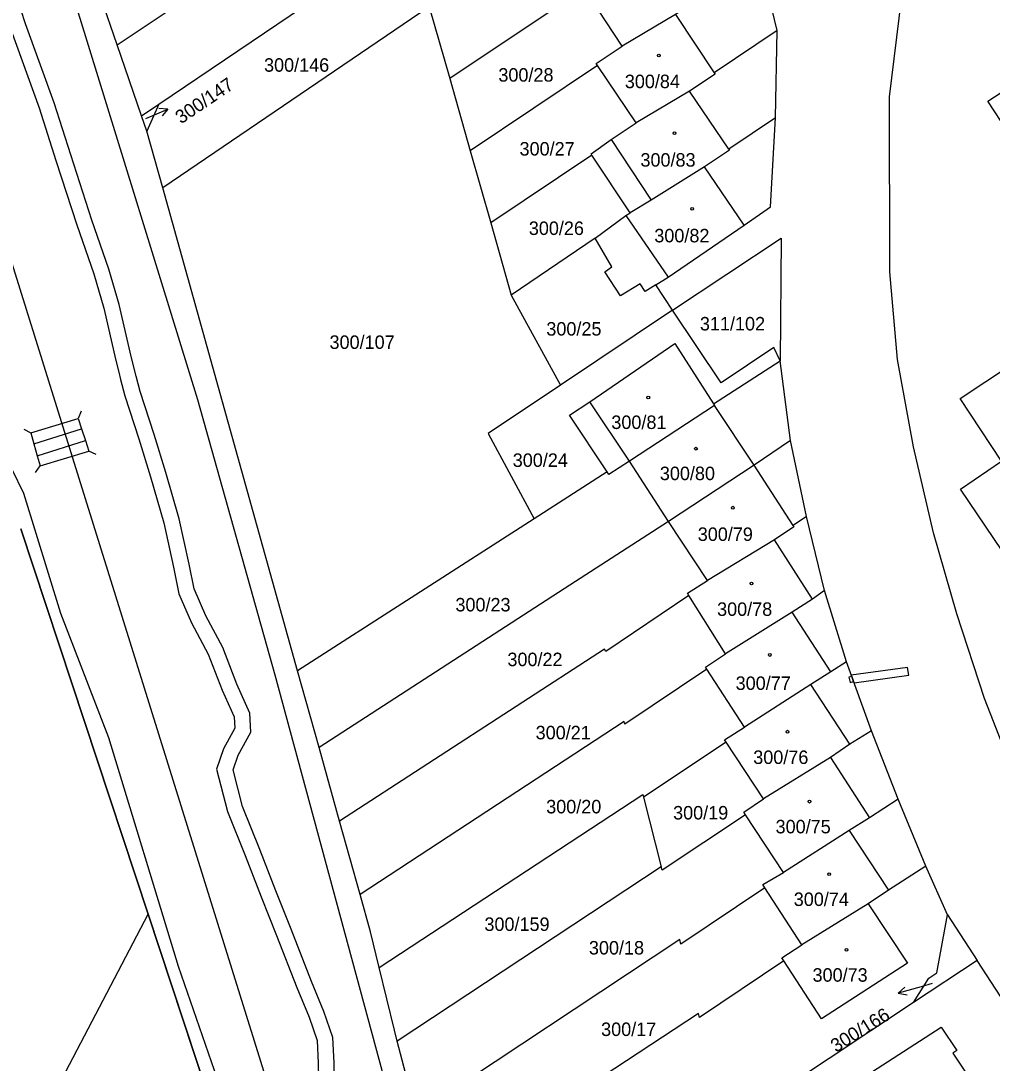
# Model space of a CAD drawing. Extents: x -757266 to -753360, y -1162585 to -1157740.
# Drawn here: x -754708.9 to -754586.4, y -1160910.2 to -1160778.7 of the extents above; entities that cross this region are included whole.
import ezdxf

# ---------------------------------------------------------------- set-up
doc = ezdxf.new("R2010")
doc.units = 0
for name, color, linetype in [('Hranice parcel', 7, 'Continuous'), ('Parcelní čísla', 7, 'Continuous'), ('Pop  PČ popisy', 7, 'Continuous'), ('Poz předměty', 7, 'Continuous'), ('Vnitřní kresba', 7, 'Continuous'), ('Věcná břemena k části', 7, 'Continuous'), ('Značky budov', 7, 'Continuous')]:
    doc.layers.add(name, color=color, linetype=linetype)

msp = doc.modelspace()

# ---------------------------------------------------------------- linework, layer by layer
at = {"layer": 'Hranice parcel'}
for p, q in [((-754691.5, -1160789.21), (-754660, -1160767.91)), ((-754613.5, -1160779.93), (-754615.74, -1160770.63)), ((-754696.76, -1160781.74), (-754699.8, -1160772.96)), ((-754637.84, -1160774.62), (-754654.81, -1160785.98)), ((-754633.05, -1160781.91), (-754637.84, -1160774.62)), ((-754657.41, -1160776.94), (-754691, -1160799.75)), ((-754657.41, -1160776.94), (-754654.81, -1160785.98)), ((-754613.7, -1160790.93), (-754613.5, -1160779.93)), ((-754693.67, -1160790.67), (-754696.76, -1160781.74)), ((-754636.17, -1160784.32), (-754652.22, -1160795.08)), ((-754631.27, -1160791.55), (-754636.17, -1160784.32)), ((-754654.81, -1160785.98), (-754652.22, -1160795.08)), ((-754693.67, -1160790.67), (-754691.5, -1160789.21)), ((-754691.5, -1160789.21), (-754693, -1160792.6)), ((-754693, -1160792.6), (-754693.67, -1160790.67)), ((-754691, -1160799.75), (-754693, -1160792.6)), ((-754652.22, -1160795.08), (-754649.63, -1160804.18)), ((-754636.89, -1160795.63), (-754649.63, -1160804.18)), ((-754632.05, -1160802.93), (-754636.89, -1160795.63)), ((-754673.99, -1160860.69), (-754691, -1160799.75)), ((-754649.63, -1160804.18), (-754647.04, -1160813.28)), ((-754636.44, -1160806.11), (-754647.04, -1160813.28)), ((-754626.69, -1160815.2), (-754628.82, -1160812.01)), ((-754647.04, -1160813.28), (-754640.82, -1160824.65)), ((-754626.69, -1160815.2), (-754640.82, -1160824.65)), ((-754621.54, -1160826.99), (-754613.13, -1160821.59)), ((-754611.82, -1160831.65), (-754613.13, -1160821.59)), ((-754609.79, -1160841.21), (-754611.82, -1160831.65)), ((-754627.23, -1160841.83), (-754632.14, -1160834.25)), ((-754634.93, -1160835.59), (-754644.16, -1160841.51)), ((-754644.16, -1160841.51), (-754673.99, -1160860.69)), ((-754622.29, -1160849.28), (-754627.23, -1160841.83)), ((-754607.52, -1160850.55), (-754609.79, -1160841.21)), ((-754692.83, -1160891.37), (-754708.93, -1160842.79)), ((-754620.01, -1160858.55), (-754624.64, -1160851.19)), ((-754604.77, -1160859.53), (-754607.52, -1160850.55)), ((-754617.64, -1160867.78), (-754622.37, -1160860.48)), ((-754601.6, -1160868.25), (-754604.77, -1160859.53)), ((-754671.29, -1160870.37), (-754673.99, -1160860.69)), ((-754598.25, -1160876.86), (-754601.6, -1160868.25)), ((-754619.95, -1160869.68), (-754630.36, -1160876.63)), ((-754615.22, -1160876.84), (-754619.95, -1160869.68)), ((-754668.7, -1160879.64), (-754671.29, -1160870.37)), ((-754630.36, -1160876.63), (-754628.12, -1160885.41)), ((-754594.76, -1160885.31), (-754598.25, -1160876.86)), ((-754612.72, -1160886.13), (-754617.5, -1160878.84)), ((-754666.11, -1160888.91), (-754668.7, -1160879.64)), ((-754628.12, -1160885.41), (-754661.42, -1160907.39)), ((-754592.02, -1160891.44), (-754594.76, -1160885.31)), ((-754610.37, -1160895.26), (-754615.04, -1160888.07)), ((-754602.01, -1160890.07), (-754610.37, -1160895.26)), ((-754682.09, -1160923.95), (-754692.83, -1160891.37)), ((-754592.02, -1160891.44), (-754588.28, -1160897.22)), ((-754588.28, -1160897.22), (-754596.29, -1160902.52)), ((-754596.29, -1160902.52), (-754652.75, -1160939.92)), ((-754659.05, -1160916.59), (-754661.42, -1160907.39))]:
    msp.add_line(p, q, dxfattribs=at)
for points in [[(-754832.33, -1160557.56), (-754811.8, -1160581.2), (-754788.57, -1160609.52), (-754757.81, -1160649.38), (-754749.73, -1160667.84), (-754718.09, -1160730.78), (-754707.28, -1160759.93), (-754701.46, -1160778.37), (-754686.64, -1160826.48), (-754676.87, -1160861.18), (-754663.2, -1160911.68), (-754637.02, -1161012.69), (-754632.76, -1161025.61)], [(-754696.76, -1160781.74), (-754684.54, -1160773.53), (-754666.73, -1160761.57)], [(-754615.74, -1160770.63), (-754623.19, -1160775.63), (-754623.11, -1160775.75), (-754626.33, -1160777.91), (-754633.05, -1160781.91)], [(-754581.21, -1160875.9), (-754581.56, -1160875.07), (-754582.98, -1160875.37), (-754587.35, -1160864.18), (-754590.82, -1160853.48), (-754593.79, -1160843.27), (-754596.29, -1160832.41), (-754598.32, -1160821.41), (-754599.28, -1160810.34), (-754599.33, -1160788.28), (-754597.8, -1160775.92), (-754589.43, -1160770.16), (-754577.92, -1160773.39), (-754576.46, -1160777.93), (-754572.43, -1160775.79), (-754571.47, -1160775.25), (-754550.32, -1160781.36), (-754545.63, -1160789.04)], [(-754613.5, -1160779.93), (-754621.45, -1160785.27), (-754621.34, -1160785.43), (-754624.57, -1160787.58), (-754631.27, -1160791.55)], [(-754636.17, -1160784.32), (-754636.32, -1160784.1), (-754633.05, -1160781.91)], [(-754584.43, -1160792.62), (-754586.94, -1160788.84), (-754576.72, -1160782.18)], [(-754636.89, -1160795.63), (-754636.98, -1160795.49), (-754634.46, -1160793.68), (-754631.27, -1160791.55)], [(-754613.7, -1160790.93), (-754619.59, -1160794.88), (-754619.5, -1160795.01), (-754622.65, -1160797.13), (-754629.4, -1160801.3), (-754632.05, -1160802.93)], [(-754628.82, -1160812.01), (-754627.24, -1160811.02), (-754617.66, -1160804.49), (-754614.36, -1160802.15), (-754613.7, -1160790.93)], [(-754636.44, -1160806.11), (-754632.58, -1160803.27), (-754632.05, -1160802.93)], [(-754628.82, -1160812.01), (-754630.17, -1160812.85), (-754630.78, -1160811.87), (-754633.26, -1160813.38), (-754635.25, -1160810.35), (-754634.34, -1160809.72), (-754636.44, -1160806.11)], [(-754626.69, -1160815.2), (-754612.98, -1160806.11), (-754613.13, -1160821.59)], [(-754579.77, -1160853.45), (-754590.36, -1160837.75), (-754585.2, -1160834.24), (-754590.43, -1160826.33), (-754567.5, -1160811.16)], [(-754613.13, -1160821.59), (-754613.92, -1160819.9), (-754620.57, -1160824.35), (-754626.69, -1160815.2)], [(-754634.93, -1160835.59), (-754639.68, -1160828.42), (-754637.14, -1160826.74), (-754626.41, -1160819.4), (-754621.54, -1160826.99)], [(-754640.82, -1160824.65), (-754649.97, -1160830.76), (-754644.16, -1160841.51)], [(-754621.54, -1160826.99), (-754621.4, -1160827.2), (-754632.14, -1160834.25)], [(-754611.82, -1160831.65), (-754616.4, -1160834.73), (-754627.23, -1160841.83)], [(-754632.14, -1160834.25), (-754634.72, -1160835.9), (-754634.93, -1160835.59)], [(-754627.23, -1160841.83), (-754639.65, -1160849.87), (-754671.29, -1160870.37)], [(-754609.79, -1160841.21), (-754611.49, -1160842.35), (-754611.38, -1160842.52), (-754613.84, -1160844.17), (-754622.29, -1160849.28)], [(-754624.64, -1160851.19), (-754624.83, -1160850.89), (-754622.29, -1160849.28)], [(-754624.64, -1160851.19), (-754635.13, -1160858.23), (-754635.28, -1160857.96), (-754668.7, -1160879.64)], [(-754607.52, -1160850.55), (-754609.06, -1160851.63), (-754611.63, -1160853.3), (-754620.01, -1160858.55)], [(-754622.37, -1160860.48), (-754622.54, -1160860.21), (-754620.01, -1160858.55)], [(-754622.37, -1160860.48), (-754632.72, -1160867.4), (-754632.81, -1160867.06), (-754666.11, -1160888.91)], [(-754604.77, -1160859.53), (-754606.75, -1160860.79), (-754609.27, -1160862.41), (-754617.64, -1160867.78)], [(-754619.95, -1160869.68), (-754620.15, -1160869.38), (-754617.64, -1160867.78)], [(-754601.6, -1160868.25), (-754604.32, -1160869.93), (-754606.77, -1160871.63), (-754615.22, -1160876.84)], [(-754663.7, -1160898.1), (-754630.45, -1160876.27), (-754630.36, -1160876.63)], [(-754617.5, -1160878.84), (-754617.71, -1160878.52), (-754615.22, -1160876.84)], [(-754598.25, -1160876.86), (-754601.84, -1160879.22), (-754604.4, -1160880.82), (-754612.72, -1160886.13)], [(-754617.5, -1160878.84), (-754628.01, -1160885.84), (-754628.12, -1160885.41)], [(-754594.76, -1160885.31), (-754599.47, -1160888.35), (-754602.01, -1160890.07)], [(-754615.04, -1160888.07), (-754615.3, -1160887.65), (-754612.72, -1160886.13)], [(-754615.04, -1160888.07), (-754625.64, -1160895.15), (-754625.79, -1160894.57), (-754659.05, -1160916.59)], [(-754663.7, -1160898.1), (-754664.8, -1160893.6), (-754666.11, -1160888.91)], [(-754602.01, -1160890.07), (-754597.07, -1160897.57), (-754607.92, -1160904.56), (-754612.66, -1160897.27)], [(-754751.88, -1161002.67), (-754733.49, -1160968.99), (-754692.83, -1160891.37)], [(-754596.29, -1160902.52), (-754594.36, -1160899.46), (-754593.35, -1160898.79), (-754592.02, -1160891.44)], [(-754612.66, -1160897.27), (-754612.9, -1160896.9), (-754610.37, -1160895.26)], [(-754612.66, -1160897.27), (-754623.32, -1160904.39), (-754623.44, -1160903.92), (-754656.67, -1160925.76)], [(-754580.89, -1160908.5), (-754584.76, -1160902.66), (-754588.28, -1160897.22)], [(-754661.42, -1160907.39), (-754661.78, -1160905.99), (-754663.7, -1160898.1)], [(-754598.41, -1160920.3), (-754600.54, -1160917.11), (-754599.88, -1160916.66), (-754602.89, -1160912.15), (-754592.82, -1160905.61), (-754590.85, -1160908.56), (-754591.35, -1160908.89), (-754588.31, -1160913.44)]]:
    msp.add_lwpolyline(points, dxfattribs=at)
at = {"layer": 'Pop  PČ popisy'}
for p, q in [((-754693.13, -1160791), (-754690.368, -1160789.827)), ((-754690.368, -1160789.827), (-754691.485, -1160789.758)), ((-754690.368, -1160789.827), (-754691.094, -1160790.68)), ((-754693.14, -1160791.01), (-754693.13, -1160791)), ((-754595.34, -1160900.53), (-754598.225, -1160901.357)), ((-754598.225, -1160901.357), (-754597.4, -1160900.6)), ((-754593.97, -1160900.13), (-754595.34, -1160900.53)), ((-754598.225, -1160901.357), (-754597.124, -1160901.562))]:
    msp.add_line(p, q, dxfattribs=at)
at = {"layer": 'Poz předměty'}
msp.add_line((-754712.18, -1160802.49), (-754666.82, -1160947.92), dxfattribs=at)
at = {"layer": 'Vnitřní kresba'}
for p, q in [((-754626.33, -1160777.91), (-754621.45, -1160785.27)), ((-754619.59, -1160794.88), (-754624.57, -1160787.58)), ((-754634.46, -1160793.68), (-754629.4, -1160801.3)), ((-754617.66, -1160804.49), (-754622.65, -1160797.13)), ((-754632.58, -1160803.27), (-754627.24, -1160811.02)), ((-754632.14, -1160834.25), (-754637.14, -1160826.74)), ((-754616.4, -1160834.73), (-754621.4, -1160827.2)), ((-754707.67, -1160830.67), (-754701.66, -1160828.86)), ((-754701.66, -1160828.86), (-754701.24, -1160830.15)), ((-754701.285, -1160827.933), (-754701.659, -1160828.86)), ((-754708.553, -1160830.2), (-754707.67, -1160830.669)), ((-754707.27, -1160832.04), (-754701.24, -1160830.15)), ((-754701.24, -1160830.15), (-754700.76, -1160831.63)), ((-754707.67, -1160830.67), (-754707.27, -1160832.04)), ((-754706.83, -1160833.58), (-754700.76, -1160831.63)), ((-754700.76, -1160831.63), (-754700.32, -1160832.97)), ((-754707.27, -1160832.04), (-754706.83, -1160833.58)), ((-754706.83, -1160833.58), (-754706.47, -1160834.84)), ((-754706.47, -1160834.84), (-754700.32, -1160832.97)), ((-754699.406, -1160833.377), (-754700.32, -1160832.971)), ((-754707.044, -1160835.659), (-754706.471, -1160834.84)), ((-754611.49, -1160842.35), (-754616.4, -1160834.73)), ((-754609.06, -1160851.63), (-754613.84, -1160844.17)), ((-754606.75, -1160860.79), (-754611.63, -1160853.3)), ((-754604.32, -1160869.93), (-754609.27, -1160862.41)), ((-754606.77, -1160871.63), (-754601.84, -1160879.22)), ((-754604.4, -1160880.82), (-754599.47, -1160888.35))]:
    msp.add_line(p, q, dxfattribs=at)
at = {"layer": 'Věcná břemena k části'}
for points in [[(-754669.29, -1160915.75), (-754669.39, -1160910.11), (-754669.57, -1160906.91), (-754670.68, -1160903.66), (-754672.26, -1160899.85), (-754674.82, -1160893.27), (-754676.73, -1160888.43), (-754678.77, -1160883.21), (-754680.96, -1160877.8), (-754682.14, -1160873.17), (-754681.51, -1160871.32), (-754679.91, -1160868.41), (-754680.01, -1160866.04), (-754681.66, -1160862.35), (-754683.45, -1160857.74), (-754685.57, -1160853.74), (-754687.05, -1160850.36), (-754687.67, -1160847.23), (-754688.94, -1160841.49), (-754690.62, -1160835.68), (-754692.11, -1160830.88), (-754693.87, -1160825.45), (-754694.37, -1160823.51), (-754695, -1160821.04), (-754696.5, -1160814.47), (-754697.8, -1160810.01), (-754699.95, -1160803.83), (-754702.62, -1160795.61), (-754704.7, -1160789.04), (-754708.31, -1160779.09), (-754708.89, -1160777.41)], [(-754710.82, -1160777.97), (-754710.18, -1160779.79), (-754706.59, -1160789.69), (-754704.5, -1160796.3), (-754701.85, -1160804.45), (-754699.7, -1160810.62), (-754698.44, -1160814.96), (-754696.94, -1160821.54), (-754696.56, -1160823), (-754696.33, -1160823.92), (-754695.79, -1160826.01), (-754694.03, -1160831.43), (-754692.56, -1160836.2), (-754690.87, -1160842.01)], [(-754638.59, -1161048.19), (-754640.8, -1161039.89), (-754643.13, -1161032.74), (-754645.39, -1161029.47), (-754654.61, -1161000.97), (-754656.4, -1160998.75), (-754657.76, -1160995.71), (-754659.5, -1160990.44), (-754661.72, -1160984.36), (-754663.98, -1160975.51), (-754671.16, -1160951.93), (-754679.56, -1160925.32), (-754689.01, -1160897.97), (-754697.83, -1160869.12), (-754703.85, -1160853.47), (-754708.55, -1160838.32), (-754710.02, -1160835.27)], [(-754690.87, -1160842.01), (-754689.64, -1160847.59), (-754688.97, -1160850.97), (-754687.37, -1160854.61), (-754685.27, -1160858.58), (-754683.5, -1160863.13), (-754681.99, -1160866.5), (-754681.93, -1160867.93), (-754683.35, -1160870.5), (-754684.22, -1160873.09), (-754682.86, -1160878.43), (-754680.62, -1160883.97), (-754678.58, -1160889.19), (-754676.66, -1160894.06), (-754674.1, -1160900.64), (-754672.55, -1160904.37), (-754671.55, -1160907.3), (-754671.39, -1160910.15), (-754671.29, -1160915.8)], [(-754708.93, -1160842.79), (-754692.83, -1160891.37), (-754682.09, -1160923.95), (-754678.05, -1160936.19), (-754671.54, -1160955.94), (-754668.46, -1160965.29), (-754664.35, -1160978.13), (-754660.49, -1160990.41), (-754656.75, -1161001.59), (-754656.39, -1161001.93), (-754647.21, -1161030.35), (-754644.95, -1161033.64), (-754642.72, -1161040.43), (-754640.01, -1161050.67)]]:
    msp.add_lwpolyline(points, dxfattribs=at)
for points in [[(-754597.04, -1160860.25), (-754604.15, -1160861.22), (-754604.09, -1160861.39), (-754603.86, -1160862.03), (-754603.8, -1160862.19), (-754596.9, -1160861.24)], [(-754603.86, -1160862.03), (-754604.09, -1160861.39), (-754604.45, -1160861.5), (-754604.29, -1160862.15)]]:
    msp.add_lwpolyline(points, close=True, dxfattribs=at)
at = {"layer": 'Značky budov'}
for centre in [(-754628.4268, -1160783.0792), (-754626.4468, -1160792.8592), (-754624.2368, -1160802.4092), (-754629.7568, -1160826.2092), (-754623.7468, -1160832.6592), (-754619.0868, -1160840.1092), (-754616.7468, -1160849.6792), (-754614.4168, -1160858.6792), (-754612.1968, -1160868.3592), (-754609.4268, -1160877.1792), (-754606.9468, -1160886.3392), (-754604.7568, -1160895.8792)]:
    msp.add_circle(centre, 0.175, dxfattribs=at)

# ---------------------------------------------------------------- texts
at = {"layer": 'Parcelní čísla'}
for s, p in [('300/146', (-754678.23, -1160785.12)), ('300/28', (-754648.67, -1160786.37)), ('300/84', (-754632.72, -1160787.19)), ('300/27', (-754646, -1160795.69)), ('300/83', (-754630.75, -1160797.09)), ('300/26', (-754644.83, -1160805.71)), ('300/82', (-754629, -1160806.64)), ('300/25', (-754642.62, -1160818.4)), ('311/102', (-754623.246, -1160817.75)), ('300/107', (-754669.97, -1160820.08)), ('300/81', (-754634.42, -1160830.18)), ('300/24', (-754646.86, -1160834.96)), ('300/80', (-754628.3, -1160836.63)), ('300/79', (-754623.52, -1160844.3)), ('300/23', (-754654.09, -1160853.19)), ('300/78', (-754621.08, -1160853.75)), ('300/22', (-754647.53, -1160860.09)), ('300/77', (-754618.74, -1160863.09)), ('300/21', (-754643.97, -1160869.32)), ('300/76', (-754616.52, -1160872.43)), ('300/20', (-754642.64, -1160878.66)), ('300/19', (-754626.63, -1160879.43)), ('300/75', (-754613.7, -1160881.18)), ('300/74', (-754611.41, -1160890.34)), ('300/159', (-754650.43, -1160893.49)), ('300/18', (-754637.25, -1160896.46)), ('300/73', (-754609.04, -1160899.89)), ('300/17', (-754635.71, -1160906.74))]:
    msp.add_text(s, height=1.7, dxfattribs=at).set_placement(p)
for s, rotation, p in [('300/147', 34, (-754688.696, -1160791.761)), ('300/166', 32, (-754606.086, -1160908.872))]:
    msp.add_text(s, height=1.7, rotation=rotation, dxfattribs=at).set_placement(p)

doc.saveas('drawing.dxf')
